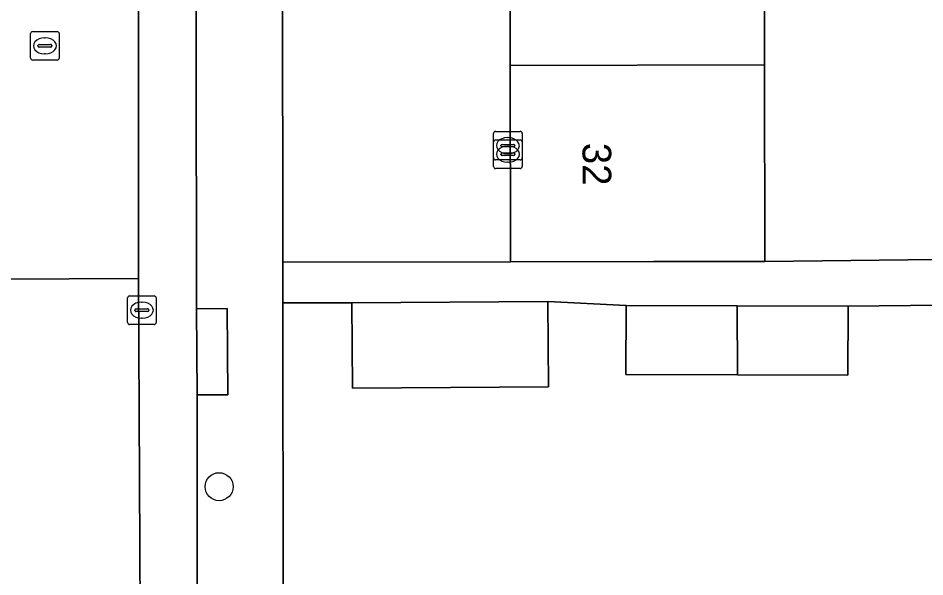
# Model space of a CAD drawing. Extents: x 160732 to 162107, y 387428 to 388479.
# Drawn here: x 161157.55 to 161189.19, y 387830.05 to 387849.56 of the extents above; entities that cross this region are included whole.
import ezdxf

# ---------------------------------------------------------------- set-up
doc = ezdxf.new("R2010")
doc.units = 0
for name, color, linetype in [('IMGEO_Boom', 7, 'Continuous'), ('IMGEO_Brandkraan', 7, 'Continuous'), ('IMGEO_Erf', 7, 'Continuous'), ('IMGEO_Kolk', 7, 'Continuous'), ('IMGEO_Pand', 7, 'Continuous'), ('IMGEO_Pand_nummerreeks', 7, 'Continuous'), ('IMGEO_Parkeervlak_open', 7, 'Continuous'), ('IMGEO_Rijbaan_lokaal_open', 7, 'Continuous'), ('IMGEO_Rioolput', 7, 'Continuous'), ('IMGEO_Voetpad_open', 7, 'Continuous')]:
    doc.layers.add(name, color=color, linetype=linetype)

msp = doc.modelspace()

# ---------------------------------------------------------------- linework, layer by layer
at = {"layer": 'IMGEO_Boom'}
msp.add_circle((161164.563, 387833.197), 0.489, dxfattribs=at)
at = {"layer": 'IMGEO_Brandkraan'}
for p, q in [((161174.135, 387844.677), (161174.135, 387845.529)), ((161174.21, 387845.603), (161175.062, 387845.603)), ((161174.623, 387845.383), (161174.648, 387845.383)), ((161175.136, 387845.529), (161175.136, 387844.677)), ((161174.394, 387845.097), (161174.394, 387845.109)), ((161174.437, 387845.146), (161174.835, 387845.146)), ((161174.878, 387845.109), (161174.878, 387845.097)), ((161174.832, 387845.06), (161174.434, 387845.06)), ((161174.646, 387844.823), (161174.621, 387844.823)), ((161175.062, 387844.603), (161174.21, 387844.603))]:
    msp.add_line(p, q, dxfattribs=at)
for points in [[(161174.135, 387844.677), (161174.135, 387845.529)], [(161174.21, 387845.603), (161175.062, 387845.603)], [(161175.136, 387845.529), (161175.136, 387844.677)], [(161175.062, 387844.603), (161174.21, 387844.603)]]:
    msp.add_lwpolyline(points, dxfattribs=at)
for centre, radius, start, end in [((161174.212, 387845.527), 0.0765, 91.552, 178.448), ((161174.212, 387845.527), 0.0765, 91.552, 178.448), ((161175.06, 387845.527), 0.0765, 1.552, 88.448), ((161175.06, 387845.527), 0.0765, 1.552, 88.448), ((161174.434, 387845.106), 0.0403, 85.8775, 175.7526), ((161174.431, 387845.096), 0.0366, 178.938, 274.7102), ((161174.835, 387845.103), 0.043, 264.8664, 352.4533), ((161174.839, 387845.108), 0.0386, 1.7309, 96.639), ((161174.212, 387844.679), 0.0765, 181.552, 268.448), ((161174.212, 387844.679), 0.0765, 181.552, 268.448), ((161175.06, 387844.679), 0.0765, 271.552, 358.448), ((161175.06, 387844.679), 0.0765, 271.552, 358.448)]:
    msp.add_arc(centre, radius, start, end, dxfattribs=at)
for centre, major_axis, ratio, start_param, end_param in [((161174.622, 387845.103), (-0.387, 0.002), 0.722429, 4.712389, 7.853982), ((161174.647, 387845.103), (-0.39, 0.002), 0.717154, 1.570796, 4.712389)]:
    msp.add_ellipse(centre, major_axis=major_axis, ratio=ratio, start_param=start_param, end_param=end_param, dxfattribs=at)
at = {"layer": 'IMGEO_Erf'}
for points in [[(161166.725, 387892.043), (161166.784, 387841.036), (161174.729, 387841.045), (161174.717, 387847.903), (161174.706, 387854.48), (161174.695, 387861.058), (161174.684, 387867.625), (161174.672, 387874.202)], [(161183.576, 387854.497), (161183.587, 387847.92), (161183.599, 387841.061), (161191.596, 387841.148), (161191.548, 387845.685), (161194.29, 387845.714), (161194.242, 387850.214)], [(161215.733, 387839.569), (161212.857, 387839.576), (161212.849, 387837.163), (161208.997, 387837.175), (161205.104, 387837.188), (161205.111, 387839.601), (161202.054, 387839.589), (161199.683, 387839.538), (161199.675, 387837.125), (161195.823, 387837.137), (161191.93, 387837.15), (161191.937, 387839.563), (161186.508, 387839.499), (161186.5, 387837.086), (161182.647, 387837.098), (161178.755, 387837.111), (161178.762, 387839.524), (161176.03, 387839.667), (161176.052, 387836.688), (161169.217, 387836.636), (161169.194, 387839.615), (161166.786, 387839.612), (161166.809, 387818.907)]]:
    msp.add_lwpolyline(points, dxfattribs=at)
at = {"layer": 'IMGEO_Kolk'}
for p, q in [((161174.137, 387844.378), (161174.137, 387845.23)), ((161174.212, 387845.304), (161175.064, 387845.304)), ((161174.625, 387845.084), (161174.65, 387845.084)), ((161175.138, 387845.23), (161175.138, 387844.378)), ((161174.396, 387844.798), (161174.396, 387844.81)), ((161174.834, 387844.761), (161174.436, 387844.761)), ((161174.439, 387844.847), (161174.837, 387844.847)), ((161174.88, 387844.81), (161174.88, 387844.798)), ((161174.648, 387844.524), (161174.623, 387844.524)), ((161175.064, 387844.304), (161174.212, 387844.304)), ((161161.366, 387838.933), (161161.366, 387839.785)), ((161161.441, 387839.859), (161162.293, 387839.859)), ((161162.367, 387839.785), (161162.367, 387838.933)), ((161161.668, 387839.402), (161162.066, 387839.402)), ((161161.854, 387839.639), (161161.879, 387839.639)), ((161161.625, 387839.353), (161161.625, 387839.365)), ((161162.063, 387839.316), (161161.665, 387839.316)), ((161161.877, 387839.079), (161161.852, 387839.079)), ((161162.109, 387839.365), (161162.109, 387839.353)), ((161162.293, 387838.859), (161161.441, 387838.859))]:
    msp.add_line(p, q, dxfattribs=at)
for points in [[(161174.137, 387844.378), (161174.137, 387845.23)], [(161174.212, 387845.304), (161175.064, 387845.304)], [(161175.138, 387845.23), (161175.138, 387844.378)], [(161175.064, 387844.304), (161174.212, 387844.304)], [(161161.366, 387838.933), (161161.366, 387839.785)], [(161161.441, 387839.859), (161162.293, 387839.859)], [(161162.367, 387839.785), (161162.367, 387838.933)], [(161162.293, 387838.859), (161161.441, 387838.859)]]:
    msp.add_lwpolyline(points, dxfattribs=at)
for centre, radius, start, end in [((161174.214, 387845.228), 0.0765, 91.552, 178.448), ((161174.214, 387845.228), 0.0765, 91.552, 178.448), ((161175.062, 387845.228), 0.0765, 1.552, 88.448), ((161175.062, 387845.228), 0.0765, 1.552, 88.448), ((161174.436, 387844.807), 0.0403, 85.8775, 175.7526), ((161174.433, 387844.797), 0.0366, 178.938, 274.7102), ((161174.837, 387844.804), 0.043, 264.8664, 352.4533), ((161174.841, 387844.809), 0.0386, 1.7309, 96.639), ((161174.214, 387844.38), 0.0765, 181.552, 268.448), ((161174.214, 387844.38), 0.0765, 181.552, 268.448), ((161175.062, 387844.38), 0.0765, 271.552, 358.448), ((161175.062, 387844.38), 0.0765, 271.552, 358.448), ((161161.443, 387839.783), 0.0765, 91.552, 178.448), ((161161.443, 387839.783), 0.0765, 91.552, 178.448), ((161162.291, 387839.783), 0.0765, 1.552, 88.448), ((161162.291, 387839.783), 0.0765, 1.552, 88.448), ((161161.665, 387839.362), 0.0403, 85.8775, 175.7526), ((161162.07, 387839.364), 0.0386, 1.7309, 96.639), ((161161.662, 387839.352), 0.0366, 178.938, 274.7102), ((161162.066, 387839.359), 0.043, 264.8664, 352.4533), ((161161.443, 387838.935), 0.0765, 181.552, 268.448), ((161161.443, 387838.935), 0.0765, 181.552, 268.448), ((161162.291, 387838.935), 0.0765, 271.552, 358.448), ((161162.291, 387838.935), 0.0765, 271.552, 358.448)]:
    msp.add_arc(centre, radius, start, end, dxfattribs=at)
for centre, major_axis, ratio, start_param, end_param in [((161174.624, 387844.804), (-0.387, 0.002), 0.722429, 4.712389, 7.853982), ((161174.649, 387844.804), (-0.39, 0.002), 0.717154, 1.570796, 4.712389), ((161161.853, 387839.359), (-0.387, 0.002), 0.722429, 4.712389, 7.853982), ((161161.878, 387839.359), (-0.39, 0.002), 0.717154, 1.570796, 4.712389)]:
    msp.add_ellipse(centre, major_axis=major_axis, ratio=ratio, start_param=start_param, end_param=end_param, dxfattribs=at)
at = {"layer": 'IMGEO_Pand'}
for points in [[(161174.706, 387854.48), (161174.717, 387847.903), (161183.587, 387847.92), (161183.576, 387854.497)], [(161174.717, 387847.903), (161174.729, 387841.045), (161179.729, 387841.054), (161183.599, 387841.061), (161183.587, 387847.92)], [(161176.052, 387836.688), (161176.03, 387839.667), (161169.194, 387839.615), (161169.217, 387836.636)], [(161178.762, 387839.524), (161178.755, 387837.111), (161182.647, 387837.098), (161182.64, 387839.511)], [(161186.5, 387837.086), (161186.508, 387839.499), (161182.64, 387839.511), (161182.647, 387837.098)]]:
    msp.add_lwpolyline(points, close=True, dxfattribs=at)
at = {"layer": 'IMGEO_Parkeervlak_open'}
for points in [[(161161.702, 387896.422), (161161.733, 387859.513), (161161.745, 387840.463), (161161.851, 387819.357)], [(161163.798, 387822.532), (161163.794, 387836.409), (161163.778, 387839.41), (161163.778, 387839.554), (161163.709, 387893.342)]]:
    msp.add_lwpolyline(points, dxfattribs=at)
at = {"layer": 'IMGEO_Rijbaan_lokaal_open'}
for points in [[(161156.862, 387841.654), (161156.899, 387840.447), (161161.745, 387840.463), (161161.733, 387859.513)], [(161161.852, 387819.236), (161161.851, 387819.357), (161161.745, 387840.463), (161156.899, 387840.447), (161156.974, 387817.523)]]:
    msp.add_lwpolyline(points, dxfattribs=at)
at = {"layer": 'IMGEO_Rioolput'}
for p, q in [((161157.984, 387848.162), (161157.984, 387849.014)), ((161158.059, 387849.088), (161158.911, 387849.088)), ((161158.472, 387848.868), (161158.497, 387848.868)), ((161158.985, 387849.014), (161158.985, 387848.162)), ((161158.243, 387848.582), (161158.243, 387848.594)), ((161158.286, 387848.631), (161158.684, 387848.631)), ((161158.727, 387848.594), (161158.727, 387848.582)), ((161158.681, 387848.545), (161158.283, 387848.545)), ((161158.495, 387848.308), (161158.47, 387848.308)), ((161158.911, 387848.088), (161158.059, 387848.088))]:
    msp.add_line(p, q, dxfattribs=at)
for points in [[(161157.984, 387848.162), (161157.984, 387849.014)], [(161158.059, 387849.088), (161158.911, 387849.088)], [(161158.985, 387849.014), (161158.985, 387848.162)], [(161158.911, 387848.088), (161158.059, 387848.088)]]:
    msp.add_lwpolyline(points, dxfattribs=at)
for centre, radius, start, end in [((161158.061, 387849.012), 0.0765, 91.552, 178.448), ((161158.061, 387849.012), 0.0765, 91.552, 178.448), ((161158.909, 387849.012), 0.0765, 1.552, 88.448), ((161158.909, 387849.012), 0.0765, 1.552, 88.448), ((161158.283, 387848.591), 0.0403, 85.8775, 175.7526), ((161158.28, 387848.581), 0.0366, 178.938, 274.7102), ((161158.684, 387848.588), 0.043, 264.8664, 352.4533), ((161158.688, 387848.593), 0.0386, 1.7309, 96.639), ((161158.061, 387848.164), 0.0765, 181.552, 268.448), ((161158.061, 387848.164), 0.0765, 181.552, 268.448), ((161158.909, 387848.164), 0.0765, 271.552, 358.448), ((161158.909, 387848.164), 0.0765, 271.552, 358.448)]:
    msp.add_arc(centre, radius, start, end, dxfattribs=at)
for centre, major_axis, ratio, start_param, end_param in [((161158.471, 387848.588), (-0.387, 0.002), 0.722429, 4.712389, 7.853982), ((161158.496, 387848.588), (-0.39, 0.002), 0.717154, 1.570796, 4.712389)]:
    msp.add_ellipse(centre, major_axis=major_axis, ratio=ratio, start_param=start_param, end_param=end_param, dxfattribs=at)
at = {"layer": 'IMGEO_Voetpad_open'}
for points in [[(161166.786, 387839.612), (161166.784, 387841.036), (161166.725, 387892.043), (161163.709, 387893.342), (161163.778, 387839.554), (161163.778, 387839.41), (161164.845, 387839.418), (161164.866, 387836.404), (161163.794, 387836.409), (161163.798, 387822.532)], [(161191.596, 387841.148), (161183.599, 387841.061), (161179.729, 387841.054), (161174.729, 387841.045), (161166.784, 387841.036), (161166.786, 387839.612), (161169.194, 387839.615), (161176.03, 387839.667), (161178.762, 387839.524), (161182.64, 387839.511), (161186.508, 387839.499), (161191.937, 387839.563)], [(161164.417, 387814.277), (161166.809, 387818.907), (161166.786, 387839.612)]]:
    msp.add_lwpolyline(points, dxfattribs=at)
msp.add_lwpolyline([(161163.778, 387839.41), (161163.794, 387836.409), (161164.866, 387836.404), (161164.845, 387839.418)], close=True, dxfattribs=at)

# ---------------------------------------------------------------- texts
at = {"layer": 'IMGEO_Pand_nummerreeks'}
msp.add_text('32', height=1, rotation=270.0981, dxfattribs=at).set_placement((161177.241, 387845.2))

doc.saveas('drawing.dxf')
